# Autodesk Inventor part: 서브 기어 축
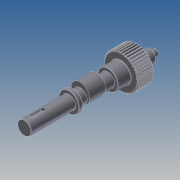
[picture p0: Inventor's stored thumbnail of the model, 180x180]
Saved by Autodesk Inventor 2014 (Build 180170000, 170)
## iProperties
Created: 2018-12
Part Number: 서브 기어 축
Material: 강철, 연강
Document SubType Name: Modeling
Designer: mduedu
Categories: <?xml version="1.0" encoding="UTF-16"?> <MemberInstance><Categories><FamilyTemplate><FamilyTemplateParameter ValueType="xs:double" Id="1" ObjectReferenceKey="da
Density: 7.86 g/cm^3
Appearance: 강철
Mass: 514.759 g
Surface Area: 160.366 cm^2
Volume: 65.491 cm^3
Author: mduedu
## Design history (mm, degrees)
sketch "Sketch1"
  geometry: C1 r 21.3 at (0, 0)
  constraints: 1 centre point
  dimensions: "d0" = 42.6 diameter of C1 (= da_da)
extrude "Extrusion1" new body sketch "Sketch1" distance "d1" = 20 (= da_b); taper "d2" = 0 deg
workplane "Work Plane2"
sketch "Sketch2"
  geometry: C1 r 21.3 at (0, 0) reference; C2 r 20.5 at (0, 0)
  constraints: 1 centre point, 1 coincident
  dimensions: "d3" = 41 diameter of C2 (= da_dw)
feature "피치 지름" sketch "Sketch2" dims "d4" = 10, "d5" = 0
workplane "Work Plane8"
workplane "Work Plane9"
chamfer "모따기1" distance "d49" = 1; stored, may be unused: second distance "d50" = 2, angle "d51" = 45 deg
sketch "스케치3"
  geometry: C1 r 12.5 at (0, 0); 1 further point
  constraints: 1 centre point, 1 coincident
  dimensions: "d52" = 25 diameter of C1
extrude "돌출2" join sketch "스케치3" distance "d53" = 16; taper "d54" = 0 deg
sketch "스케치4"
  geometry: C1 r 8.5 at (0, 0); 1 further point
  constraints: 1 centre point, 1 coincident
  dimensions: "d55" = 17 diameter of C1
extrude "돌출3" join sketch "스케치4" distance "d56" = 103; taper "d57" = 0 deg
sketch "스케치5"
  geometry: C1 r 7.5 at (0, 0); 1 further point
  constraints: 1 centre point, 1 coincident
  dimensions: "d58" = 15 diameter of C1
extrude "돌출4" join sketch "스케치5" distance "d59" = 16; taper "d60" = 0 deg
sketch "스케치6"
  geometry: C1 r 4 at (0, 0); 1 further point
  constraints: 1 centre point, 1 coincident
  dimensions: "d61" = 8 diameter of C1
extrude "돌출5" join sketch "스케치6" distance "d62" = 7; taper "d63" = 0 deg
chamfer "모따기2" distance "d64" = 0.5; stored, may be unused: second distance "d65" = 2, angle "d66" = 45 deg
fillet "모깎기1" dims "d67" = 0.5
feature "스퍼 기어" dims "da_b" = 20, "da_d" = 41, "da_aw" = 31, "da_da" = 42.6, "da_df" = 39.086, "da_dw" = 41, angle "da_beta" = 0 deg, "da_lefttooth" = 0, "da_righttooth" = 0
node "작업 평면11"
sketch "스케치7"
  geometry: C1 r 11.5 at (0, 3); C2 r 8.5 at (0, 0) reference; 1 further point
  constraints: 1 centre point, 1 tangent, 1 vertical alignment
  dimensions: "d69" = 3 distance of point (0, 0) C1.centre; "d70" = 23 diameter of C1 (derived)
extrude "돌출6" join sketch "스케치7" stored distance "d71" = 20; taper "d72" = 0 deg
node "작업 평면12"
sketch "스케치8"
  geometry: C1 r 12.5 at (0, 0) reference; C2 r 12.5 at (0, 0) reference; 1 further point
extrude "돌출7" join sketch "스케치8" distance "d74" = 5; taper "d75" = 0 deg
chamfer "모따기3" distance "d76" = 0.5; stored, may be unused: second distance "d77" = 2, angle "d78" = 45 deg
sketch "스케치9"
  geometry: L1 (-8, 139)-(8, 139) reference; L2 (0, 139)-(0, 0); L3 (-8.5, 84)-(-8.5, 138.5) reference; L4 (-8.5, 115)-(0, 115); L5 (-8.5, 115)-(-8.5, 113.5); L6 (-8.5, 113.5)-(-7, 115); L7 (-7, 115)-(-8.5, 115)
  constraints: 10 end point, 4 point on line, 2 perpendicular, 1 collinear, 1 midpoint
  dimensions: "d79" = 24 distance between parallel lines of L4 L1; "d80" = 3 diameter of L5.end L4; "d81" = 45 deg angle of L6 L3
revolve "회전1" sketch "스케치9" stored, may be unused: angle "d82" = 90 deg
sketch "스케치10"
  geometry: L1 (-8.5, 116.5)-(-7, 115) reference; L2 (-8.5, 113.5)-(-7, 115) reference; 2 further points
  constraints: 1 coincident
node "작업점1"
node "작업 평면13"
sketch "스케치11"
  geometry: L1 (-2.5, 93.5)-(-2.5, 80.5); L2 (2.5, 80.5)-(2.5, 93.5); L3 (-8, 103)-(8, 103) reference; A1 r 2.5 centre (0, 93.5) between (2.5, 93.5) and (-2.5, 93.5); A2 r 2.5 centre (0, 80.5) between (-2.5, 80.5) and (2.5, 80.5); 1 further point
  constraints: 4 end point, 4 point on circle, 4 tangent, 2 centre point, 2 vertical alignment, 1 parallel
  dimensions: "d83" = 7 distance edge to line of A1 L3; "d84" = 18 dimension on A2 A1; "d85" = 5 distance between parallel lines of L1 L2
extrude "돌출8" cut sketch "스케치11" distance "d86" = 3; taper "d87" = 0 deg
sketch "스케치12" dims "d88" = 32
  geometry: C1 r 0.5 at (0, -16); 2 further points
  constraints: 2 vertical alignment, 1 centre point, 1 coincident, 2 other
  dimensions: "d89" = 1 diameter of C1
extrude "돌출9" join sketch "스케치12" distance "d90" = 0.3; taper "d91" = 0 deg
sketch "스케치13"
  geometry: C1 r 11.5 at (0, 3) reference; 1 further point
  node "절단 모서리 투영1"
body "Solid1"
body "Srf1"
node "투영된 루프1"
other parameters: "d16" = 31 (= da_aw), "d17" = 0, "d34" = 0.76624 (computed from da_z), "d39" = 0, "d41" = 0, "d43" = 31 (= da_aw), "d46" = 31 (= da_aw), "d47" = 0, "d48" = 0, "d68" = 24, "d73" = 48
